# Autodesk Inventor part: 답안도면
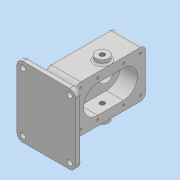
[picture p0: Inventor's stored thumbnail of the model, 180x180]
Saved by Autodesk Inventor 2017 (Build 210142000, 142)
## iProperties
Part Number: 답안도면
Material: 일반
Document SubType Name: Modeling
Designer: MRC
Density: 1 g/cm^3
Appearance: 기본값
Author: MRC
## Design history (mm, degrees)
sketch "스케치1"
  geometry: L1 (-26.5, 60)-(-26.5, -60); L2 (-26.5, -60)-(26.5, -60); L3 (-26.5, 60)-(26.5, 60); L4 (26.5, 60)-(26.5, -60); 3 further points
  constraints: 8 end point, 2 horizontal, 2 midpoint, 1 horizontal alignment, 1 vertical, 1 vertical alignment
  dimensions: "d0" = 120 distance of L1.start L1.end; "d1" = 53 distance of L1.end L2.end; "d2" = 53 distance of L1.start L3.end
extrude "돌출1" new body sketch "스케치1" stored distance "d3" = 80; taper "d4" = 0 deg
sketch "스케치2"
  geometry: L1 (40, 60)-(40, 82); L2 (40, 60)-(40, 38); L3 (40, 82)-(40, 38); L4 (16, 82)-(16, 38); L5 (64, 38)-(64, 82); A1 r 24 centre (40, 82) between (64, 82) and (16, 82); A2 r 24 centre (40, 38) between (16, 38) and (64, 38); 1 further point
  constraints: 12 end point, 4 point on circle, 4 tangent, 3 vertical, 2 centre point, 1 midpoint, 1 parallel
  dimensions: "d5" = 22 distance of L1.start L1.end; "d6" = 22 distance of L1.start L2.end; "d7" = 48 diameter of A2
extrude "돌출2" cut sketch "스케치2" distance "d8" = 29; taper "d9" = 0 deg
sketch "스케치3"
  geometry: C1 r 12.5 at (40, 82); C2 r 12.5 at (40, 38); A1 r 24 centre (40, 38) between (16, 38) and (64, 38) reference; A2 r 24 centre (40, 82) between (64, 82) and (16, 82) reference; 1 further point
  constraints: 2 centre point, 2 coincident
  dimensions: "d10" = 25 diameter of C1; "d11" = 25 diameter of C2
extrude "돌출3" cut sketch "스케치3" distance "d12" = 15; taper "d13" = 0 deg
sketch "스케치4"
  geometry: L1 (-40, 60)-(-40, 82); C1 r 19 at (-40, 82)
  constraints: 2 end point, 1 centre point, 1 coincident, 1 vertical
  dimensions: "d14" = 22 distance of L1.start L1.end; "d15" = 38 diameter of C1
extrude "돌출4" join sketch "스케치4" distance "d16" = 17; taper "d17" = 0 deg
sketch "스케치5"
  geometry: C1 r 19 at (0, 0) reference; C2 r 14 at (0, 0); 1 further point
  constraints: 1 centre point, 1 coincident
  dimensions: "d18" = 28 diameter of C2
extrude "돌출5" cut sketch "스케치5" distance "d19" = 7.3; taper "d20" = 0 deg
sketch "스케치6"
  geometry: C1 r 12.5 at (0, 0) reference; C2 r 8.5 at (0, 0); 1 further point
  constraints: 1 centre point, 1 coincident
  dimensions: "d21" = 17 diameter of C2
extrude "돌출6" cut sketch "스케치6" distance "d22" = 18.7; taper "d23" = 0 deg
node "작업 평면1"
sketch "스케치7"
  geometry: L1 (-56.5, -60)-(43.5, -60); L2 (43.5, -60)-(43.5, 60); L3 (43.5, 60)-(-56.5, 60); L4 (-56.5, 60)-(-56.5, -60); L5 (43.5, -19)-(43.5, 19) reference; 3 further points
  constraints: 8 end point, 3 midpoint, 2 parallel, 1 horizontal, 1 horizontal alignment, 1 perpendicular
  dimensions: "d25" = 100 distance of L3.end L2.end; "d26" = 120 distance of L2.end L1.end
extrude "돌출7" join sketch "스케치7" distance "d27" = 10; taper "d28" = 0 deg
fillet "모깎기1" dims "d33" = 9
fillet "모깎기2" dims "d34" = 3
sketch "스케치9"
  geometry: L1 (-26.5, -80)-(-14.953, -60); L2 (26.5, -80)-(14.953, -60); L3 (-43.5, -80)-(56.5, -80) reference; L4 (-43.5, -90)-(-43.5, -80) reference; L5 (-23.5, -60)-(26.5, -60) reference; 1 further point
  constraints: 4 end point, 4 point on line
  dimensions: "d35" = 60 deg angle of L1 L3; "d36" = 60 deg angle of L3 L2; "d37" = 17 distance from line of L1.start L4; "d38" = 53 distance of L2.start L1.start
extrude "돌출8" join sketch "스케치9" stored distance "d39" = 48; taper "d40" = 0 deg
sketch "스케치10"
  geometry: L1 (-26.5, 51)-(-26.5, -51) reference; C1 r 11 at (-12.5, 0); 1 further point
  constraints: 1 centre point, 1 horizontal alignment
  dimensions: "d41" = 22 diameter of C1; "d42" = 14 distance from line of C1.centre L1
extrude "돌출9" join sketch "스케치10" distance "d43" = 8; taper "d44" = 0 deg
hole "구멍1" diameter "d47" = 8.376; stored, may be unused: countersink angle "d51" = 90 deg, drill point angle "d53" = 118 deg; dims "d45" = 10, "d46" = 10, "d48" = 20, "d49" = 4, "d50" = 2, "d52" = 27.3
fillet "모깎기3" dims "d54" = 3
fillet "모깎기4" dims "d55" = 10
fillet "모깎기5" dims "d56" = 3
sketch "스케치11"
  geometry: A1 r 7 centre (-33.5, -50) between (-40.5, -50) and (-33.5, -57) reference; A2 r 7 centre (46.5, -50) between (46.5, -57) and (53.5, -50) reference; A3 r 7 centre (46.5, 50) between (53.5, 50) and (46.5, 57) reference; A4 r 7 centre (-33.5, 50) between (-33.5, 57) and (-40.5, 50) reference; 5 further points
  constraints: 4 coincident
hole "구멍2" sketch "스케치11" at (-33.5, 50), (46.5, 50), (46.5, -50), (-33.5, -50) diameter "d57" = 9; stored, may be unused: countersink angle "d61" = 90 deg, drill point angle "d63" = 118 deg; dims "d58" = 20, "d59" = 4, "d60" = 2, "d62" = 27.3
chamfer "모따기1" distance "d64" = 0.7; stored, may be unused: second distance "d65" = 2, angle "d66" = 30 deg
chamfer "모따기2" distance "d67" = 1; stored, may be unused: second distance "d68" = 2, angle "d69" = 30 deg
sketch "스케치12"
  geometry: L1 (-33.5, -60)-(46.5, -60) reference; L2 (56.5, -50)-(56.5, 50) reference; 2 further points
  constraints: 1 other
  dimensions: "d70" = 60 distance from line of L1 point (46.5, 0); "d71" = 10 distance from line of L2 point (46.5, 0)
feature "엠보싱1" sketch "스케치12" dims "d0" = 120, "d1" = 53, "d2" = 53, "d72" = 0.5, "d73" = 0
sketch "스케치13"
  geometry: A1 r 9 centre (62, -111) between (62, -120) and (71, -111) reference; A2 r 9 centre (62, -9) between (71, -9) and (62, 0) reference; A3 r 9 centre (0, -9) between (0, 0) and (-9, -9) reference; A4 r 9 centre (0, -111) between (-9, -111) and (0, -120) reference; 9 further points
  constraints: 4 coincident, 4 vertical alignment, 2 horizontal alignment
  dimensions: "d74" = 29 distance of point (0, -38) point (0, -9); "d75" = 29 distance of point (0, -111) point (0, -82)
hole "구멍3" sketch "스케치13" at (0, -9), (62, -9), (0, -111), (62, -111), (0, -38), (0, -82), (62, -38), (62, -82) diameter "d76" = 4.134; stored, may be unused: countersink angle "d80" = 90 deg, drill point angle "d82" = 118 deg; dims "d77" = 10, "d78" = 4, "d79" = 2, "d81" = 12
fillet "모깎기6" dims "d83" = 0.5
node "솔리드1"
mirror "미러1"
